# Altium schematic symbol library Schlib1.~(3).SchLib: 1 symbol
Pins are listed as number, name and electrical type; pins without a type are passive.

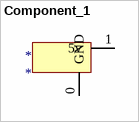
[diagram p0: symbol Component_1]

## Component_1
designator *
pins: 0 GND (power), 1 5v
